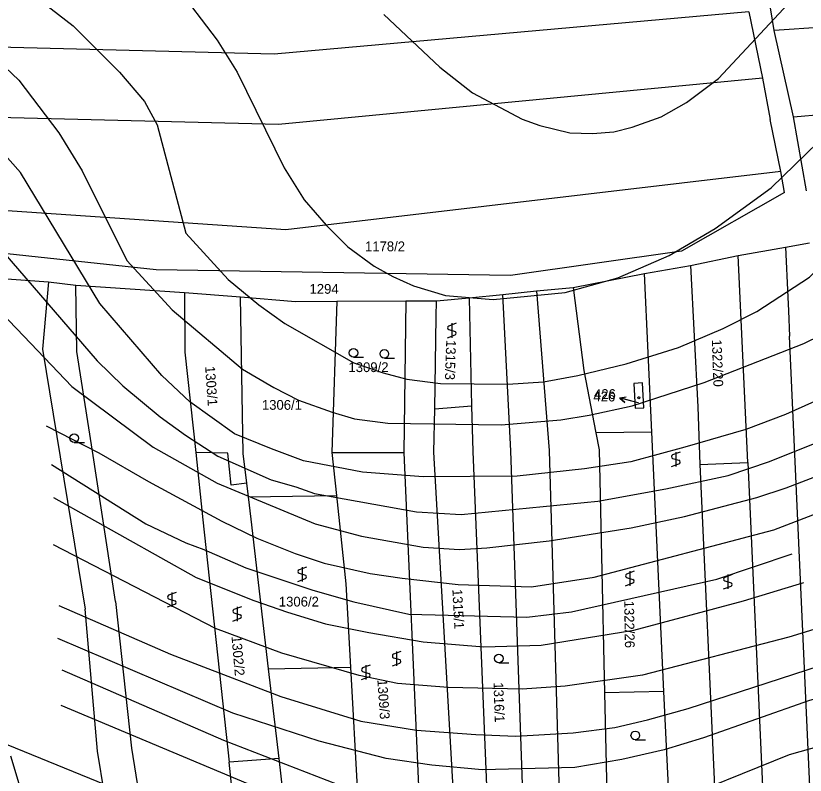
# Model space of a CAD drawing. Extents: x -555860 to -552701, y -1187050 to -1182291.
# Drawn here: x -554030 to -553892.9, y -1185037.6 to -1184905.7 of the extents above; entities that cross this region are included whole.
import ezdxf

# ---------------------------------------------------------------- set-up
doc = ezdxf.new("R2010")
doc.units = 0
for name, color, linetype in [('CYKLISTI_stav', 7, 'Continuous'), ('LEG_2b', 7, 'Continuous'), ('Level 16', 7, 'Continuous'), ('Level 25', 7, 'Continuous'), ('Level 40', 7, 'Continuous'), ('Level 41', 7, 'Continuous'), ('navrh_BV', 7, 'Continuous'), ('stav_BV', 7, 'Continuous')]:
    doc.layers.add(name, color=color, linetype=linetype)

msp = doc.modelspace()

# ---------------------------------------------------------------- linework, layer by layer
at = {"layer": 'CYKLISTI_stav'}
for p, q in [((-553921.18, -1184969.45), (-553922.68, -1184969.52)), ((-553922.68, -1184969.52), (-553922.47, -1184973.82)), ((-553920.98, -1184973.75), (-553921.18, -1184969.45)), ((-553922.47, -1184973.82), (-553920.98, -1184973.75))]:
    msp.add_line(p, q, dxfattribs=at)
at = {"layer": 'Level 16'}
for p, q in [((-553925.1, -1184972.09), (-553924.01, -1184971.85)), ((-553922.2, -1184972.84), (-553925.1, -1184972.09)), ((-553925.1, -1184972.09), (-553924.26, -1184972.82))]:
    msp.add_line(p, q, dxfattribs=at)
msp.add_lwpolyline([(-553921.89, -1184972.92), (-553922.2, -1184972.84)], dxfattribs=at)
at = {"layer": 'Level 25'}
for p, q in [((-553953.53, -1184959.09), (-553954.83, -1184959.56)), ((-553954.28, -1184959.09), (-553954.28, -1184961.59)), ((-553955.03, -1184961.59), (-553953.73, -1184961.1)), ((-553954.83, -1184960.17), (-553953.73, -1184960.5)), ((-553971.38, -1184964.95), (-553969.63, -1184964.95)), ((-553966.02, -1184965.15), (-553964.27, -1184965.15)), ((-554019.86, -1184979.8), (-554018.11, -1184979.8)), ((-553914.67, -1184981.47), (-553915.97, -1184981.95)), ((-553915.42, -1184981.47), (-553915.42, -1184983.97)), ((-553915.97, -1184982.55), (-553914.87, -1184982.88)), ((-553916.17, -1184983.97), (-553914.87, -1184983.48)), ((-553979.52, -1185001.42), (-553980.82, -1185001.9)), ((-553980.82, -1185002.5), (-553979.72, -1185002.83)), ((-553980.27, -1185001.42), (-553980.27, -1185003.92)), ((-553922.65, -1185002.16), (-553923.95, -1185002.64)), ((-553923.4, -1185002.16), (-553923.4, -1185004.66)), ((-553981.02, -1185003.92), (-553979.72, -1185003.43)), ((-553923.95, -1185003.24), (-553922.85, -1185003.57)), ((-553905.62, -1185002.73), (-553906.92, -1185003.21)), ((-553906.92, -1185003.81), (-553905.82, -1185004.14)), ((-553906.37, -1185002.73), (-553906.37, -1185005.23)), ((-553924.15, -1185004.66), (-553922.85, -1185004.17)), ((-553907.12, -1185005.23), (-553905.82, -1185004.74)), ((-554002.19, -1185005.85), (-554003.49, -1185006.32)), ((-554002.94, -1185005.85), (-554002.94, -1185008.35)), ((-554003.69, -1185008.35), (-554002.39, -1185007.86)), ((-554003.49, -1185006.93), (-554002.39, -1185007.26)), ((-553990.85, -1185008.31), (-553992.15, -1185008.78)), ((-553992.15, -1185009.39), (-553991.05, -1185009.72)), ((-553991.6, -1185008.31), (-553991.6, -1185010.81)), ((-553992.35, -1185010.81), (-553991.05, -1185010.32)), ((-553963.13, -1185016.09), (-553964.43, -1185016.56)), ((-553963.88, -1185016.09), (-553963.88, -1185018.59)), ((-553964.43, -1185017.17), (-553963.33, -1185017.5)), ((-553968.5, -1185018.47), (-553969.8, -1185018.95)), ((-553969.25, -1185018.47), (-553969.25, -1185020.97)), ((-553964.63, -1185018.59), (-553963.33, -1185018.1)), ((-553946.14, -1185018.04), (-553944.39, -1185018.04)), ((-553969.8, -1185019.55), (-553968.7, -1185019.88)), ((-553970, -1185020.97), (-553968.7, -1185020.48)), ((-553922.44, -1185031.4), (-553920.69, -1185031.4))]:
    msp.add_line(p, q, dxfattribs=at)
for centre, radius in [((-553971.38, -1184964.2), 0.75), ((-553966.02, -1184964.4), 0.75), ((-553921.84, -1184972.01), 0.175), ((-554019.86, -1184979.05), 0.75), ((-553946.14, -1185017.29), 0.75), ((-553922.44, -1185030.65), 0.75)]:
    msp.add_circle(centre, radius, dxfattribs=at)
for centre, start, end in [((-553954.7, -1184959.87), 113.579, 246.421), ((-553953.86, -1184960.8), 293.574, 66.426), ((-553915.84, -1184982.25), 113.579, 246.421), ((-553915, -1184983.18), 293.574, 66.426), ((-553980.69, -1185002.2), 113.579, 246.421), ((-553979.85, -1185003.13), 293.574, 66.426), ((-553923.82, -1185002.94), 113.579, 246.421), ((-553922.98, -1185003.87), 293.574, 66.426), ((-553906.79, -1185003.51), 113.579, 246.421), ((-553905.95, -1185004.44), 293.574, 66.426), ((-554003.36, -1185006.63), 113.579, 246.421), ((-554002.52, -1185007.56), 293.574, 66.426), ((-553992.02, -1185009.09), 113.579, 246.421), ((-553991.18, -1185010.02), 293.574, 66.426), ((-553964.3, -1185016.87), 113.579, 246.421), ((-553963.46, -1185017.8), 293.574, 66.426), ((-553969.67, -1185019.25), 113.579, 246.421), ((-553968.83, -1185020.18), 293.574, 66.426)]:
    msp.add_arc(centre, 0.329, start, end, dxfattribs=at)
at = {"layer": 'Level 40'}
for points in [[(-553846.88, -1184943.12), (-553856.95, -1184950.02), (-553865.7, -1184957.05), (-553875.27, -1184964.12), (-553882.93, -1184968.93), (-553896.35, -1184974.93), (-553903.23, -1184977.51), (-553913.82, -1184980.62), (-553923.19, -1184983.12), (-553931.29, -1184984.36), (-553942.94, -1184985.61), (-553959.3, -1184985.75), (-553969.84, -1184984.92), (-553980.08, -1184982.96), (-553985.64, -1184980.9), (-553992.02, -1184978.26), (-553999.79, -1184972.71), (-554004.64, -1184968.14), (-554015.45, -1184955.66), (-554029.18, -1184932.92), (-554034.17, -1184927.37)], [(-554023.46, -1184989.37), (-553998.68, -1185003.22), (-553988.69, -1185007.24), (-553982.85, -1185009.28), (-553976.25, -1185011.26), (-553968.73, -1185012.79), (-553959.26, -1185014.4), (-553948.76, -1185015.28), (-553938.78, -1185015), (-553922.69, -1185012.37), (-553903.68, -1185007.3), (-553893.18, -1185004.13)], [(-554022.18, -1185025.41), (-553989.8, -1185038.99), (-553977.32, -1185044.82), (-553969, -1185049.53), (-553958.76, -1185054.33), (-553952.37, -1185056.88), (-553948.86, -1185057.47), (-553939.61, -1185058.41), (-553931.9, -1185057.79), (-553926.02, -1185056.88), (-553916.59, -1185054.11), (-553894.27, -1185043.84), (-553880.54, -1185039.41), (-553873.48, -1185038.49), (-553866.4, -1185038.85), (-553841.44, -1185043.98), (-553838.37, -1185043.93), (-553834.92, -1185043.15), (-553828.96, -1185039.27), (-553800.95, -1185016.25)]]:
    msp.add_lwpolyline(points, dxfattribs=at)
at = {"layer": 'Level 41'}
for points in [[(-554029.46, -1184900.06), (-554020.03, -1184907.41), (-554011.99, -1184915.45), (-554007.69, -1184920.58), (-554005.47, -1184924.6), (-554000.48, -1184943.46), (-553993.13, -1184951.5), (-553987.84, -1184955.9), (-553983.29, -1184959.13), (-553971.34, -1184965.96), (-553966.23, -1184967.72), (-553962.1, -1184968.77), (-553956.25, -1184969.53), (-553944.6, -1184969.66), (-553938.37, -1184969.26), (-553932.4, -1184968.14), (-553924.02, -1184966.13), (-553914.93, -1184963.28), (-553907.19, -1184960.02), (-553901.34, -1184957.05), (-553892.19, -1184951.08), (-553878.57, -1184937.71)], [(-554002.28, -1184900.34), (-553995.07, -1184909.9), (-553991.6, -1184915.45), (-553983.42, -1184932.09), (-553979.96, -1184937.64), (-553976.12, -1184942.03), (-553972.33, -1184945.81), (-553967.76, -1184949.14), (-553964.57, -1184950.95), (-553960.96, -1184952.61), (-553955.42, -1184954.27), (-553947.1, -1184954.97), (-553934.62, -1184953.72), (-553925.47, -1184951.22), (-553916.59, -1184947.34), (-553908.55, -1184942.63), (-553898.84, -1184935.55), (-553890.69, -1184927.64)], [(-553966.09, -1184905.47), (-553956.39, -1184914.62), (-553950.7, -1184919.05), (-553942.1, -1184923.63), (-553939.03, -1184924.71), (-553933.79, -1184925.99), (-553929.9, -1184926.13), (-553926.16, -1184925.86), (-553922.97, -1184925.02), (-553917.98, -1184923.21), (-553913.54, -1184920.72), (-553907.99, -1184916.56), (-553893.49, -1184900.97)], [(-554037.78, -1184909.07), (-554029.46, -1184916.84), (-554022.53, -1184925.99), (-554018.51, -1184932.64), (-554010.74, -1184948.17), (-554002.84, -1184956.77), (-553990.64, -1184967.03), (-553985.2, -1184970.25), (-553980.93, -1184972.44), (-553975.1, -1184974.52), (-553971.18, -1184975.7), (-553965.4, -1184976.46), (-553945.71, -1184976.74), (-553935.4, -1184975.86), (-553930.46, -1184975.07), (-553922.97, -1184973.41), (-553910.49, -1184969.39), (-553893.16, -1184962.59), (-553884.42, -1184958.29)], [(-554037.08, -1184941.1), (-554015.89, -1184965.63), (-554011.43, -1184969.94), (-554004.92, -1184975.35), (-554000.55, -1184978.5), (-553994.93, -1184982.14), (-553985.7, -1184986.26), (-553981.37, -1184987.5), (-553978.16, -1184988.66), (-553960.41, -1184991.85), (-553952.66, -1184992.29), (-553928.93, -1184989.98), (-553917.15, -1184987.83), (-553906.32, -1184985.52), (-553899.12, -1184983.11), (-553887.72, -1184978.5), (-553878.05, -1184974.24), (-553865.11, -1184966.46), (-553856.83, -1184961.07), (-553838.49, -1184947.41)], [(-554044.57, -1184944.71), (-554028.63, -1184961.34), (-554020.31, -1184970.08), (-554006.16, -1184980.62), (-553995.07, -1184986.86), (-553978.02, -1184993.93), (-553969.98, -1184996.08), (-553959.3, -1184997.95), (-553952.98, -1184998.39), (-553948.21, -1184998.09), (-553937.39, -1184996.84), (-553923.15, -1184994.6), (-553913.91, -1184992.62), (-553901.34, -1184989.35), (-553896.26, -1184987.67), (-553887.33, -1184984.22), (-553866.81, -1184975.63), (-553856.83, -1184970.64), (-553837.97, -1184957.88), (-553831.32, -1184953.92), (-553823, -1184949.56), (-553815.94, -1184946.67)], [(-554024.76, -1184976.88), (-554015.59, -1184981.59), (-554006.98, -1184986.59), (-553994.24, -1184993.44), (-553988.14, -1184996.43), (-553981.53, -1184999.05), (-553976.49, -1185000.72), (-553968.5, -1185002.52), (-553962.9, -1185003.36), (-553953.2, -1185004.47), (-553940.44, -1185004.88), (-553929.59, -1185003.18), (-553898.4, -1184994.93), (-553882.89, -1184988.99), (-553868.24, -1184982.79), (-553853.23, -1184977.02), (-553838.11, -1184966.48), (-553825.08, -1184958.99), (-553814.82, -1184954.57), (-553806.5, -1184951.22), (-553801.95, -1184950.12)], [(-553748.88, -1184982.14), (-553757.97, -1184976.46), (-553763.99, -1184974.21), (-553770.17, -1184972.57), (-553776.86, -1184972.07), (-553781.82, -1184971.88), (-553788.58, -1184972.73), (-553795.13, -1184973.96), (-553805.11, -1184977.43), (-553816.2, -1184982.7), (-553837.56, -1184994.07), (-553851.15, -1184999.89), (-553895.79, -1185013.62), (-553921.17, -1185020.17), (-553934.62, -1185022.08), (-553942.1, -1185022.63), (-553954.96, -1185022.32), (-553963.73, -1185021.66), (-553970.39, -1185020.27), (-553983.84, -1185016.38), (-553995.35, -1185012.09), (-554023.46, -1184997.58)], [(-554022.56, -1185008.07), (-554003.15, -1185016.54), (-553983.98, -1185023.88), (-553970.11, -1185028.18), (-553960.41, -1185029.74), (-553950.15, -1185030.53), (-553943.21, -1185030.81), (-553933.22, -1185030.24), (-553926.02, -1185029.29), (-553920.35, -1185027.93), (-553913.26, -1185025.96), (-553885.81, -1185017.08), (-553874.16, -1185014.03), (-553856.69, -1185011.12), (-553846.99, -1185008.63), (-553830.35, -1185001.83), (-553804.28, -1184987.55), (-553789.86, -1184981.86)], [(-554023.83, -1184983.59), (-554007.41, -1184993.93), (-554000.51, -1184997.24), (-553997.37, -1184998.39), (-553990.08, -1185001.55), (-553978.43, -1185005.44), (-553971.3, -1185007.47), (-553961.79, -1185009.6), (-553941.27, -1185010.15), (-553933.51, -1185009.18), (-553908.27, -1185003.5), (-553895.23, -1184999.15)], [(-553798.18, -1184992.68), (-553811.77, -1184999.06), (-553835.89, -1185013.9), (-553841.72, -1185016.53), (-553845.8, -1185018.03), (-553859.19, -1185019.72), (-553872.78, -1185020.14), (-553878.6, -1185020.97), (-553892.19, -1185024.57), (-553910.61, -1185031.06), (-553917.42, -1185033.17), (-553924.8, -1185034.86), (-553932.95, -1185036.22), (-553949.04, -1185036.64), (-553957.77, -1185035.85), (-553965.68, -1185034.69), (-553977.32, -1185031.64), (-553992.3, -1185026.79), (-554022.74, -1185013.85)], [(-554022, -1185019.26), (-553993.96, -1185031.5), (-553963.46, -1185043.29), (-553953.47, -1185046.48), (-553949.35, -1185047.23), (-553941.27, -1185047.45), (-553932.56, -1185046.57), (-553926.02, -1185045.09), (-553917.7, -1185042.87), (-553895.65, -1185034), (-553884.98, -1185030.95), (-553873.33, -1185029.01), (-553868.86, -1185028.92), (-553863.9, -1185029.29), (-553857.8, -1185030.12), (-553849.48, -1185030.95), (-553844.21, -1185030.67), (-553838.39, -1185029.43), (-553832.6, -1185027.27), (-553828.27, -1185024.99), (-553810.66, -1185009.88), (-553801.37, -1185003.36)], [(-554002.98, -1185043.93), (-554038.61, -1185029.43)]]:
    msp.add_lwpolyline(points, dxfattribs=at)
at = {"layer": 'navrh_BV'}
for p, q in [((-553898.35, -1184908.26), (-553900.51, -1184894.48)), ((-553902.74, -1184905), (-553985.15, -1184912.34)), ((-553902.74, -1184905), (-553900.36, -1184916.5)), ((-553841.58, -1184904.41), (-553898.35, -1184908.26)), ((-553894.95, -1184923.21), (-553898.35, -1184908.26)), ((-553985.15, -1184912.34), (-554037.67, -1184911.01)), ((-553900.36, -1184916.5), (-553984.42, -1184924.58)), ((-553900.36, -1184916.5), (-553899.04, -1184923.67)), ((-553894.95, -1184923.21), (-553841.03, -1184918.7)), ((-553984.42, -1184924.58), (-554037.31, -1184923.26)), ((-553897.19, -1184932.74), (-553899.04, -1184923.67)), ((-553892.7, -1184936.1), (-553894.95, -1184923.21)), ((-553897.19, -1184932.74), (-553983.1, -1184942.85)), ((-553896.54, -1184936.39), (-553897.19, -1184932.74)), ((-553896.54, -1184936.39), (-553914.4, -1184946.57)), ((-553983.1, -1184942.85), (-554037.78, -1184939.14)), ((-554005.64, -1184949.81), (-554060.2, -1184943.98)), ((-553904.57, -1184947.31), (-553896.35, -1184945.85)), ((-553896.35, -1184945.85), (-553892.21, -1184945.11)), ((-553896.35, -1184945.85), (-553895.96, -1184954.54)), ((-553914.4, -1184946.57), (-553944.13, -1184950.79)), ((-553912.83, -1184949.06), (-553904.57, -1184947.31)), ((-553902.92, -1184983.27), (-553904.57, -1184947.31)), ((-553920.87, -1184950.42), (-553912.83, -1184949.06)), ((-553912.83, -1184949.06), (-553911.57, -1184973.61)), ((-553944.13, -1184950.79), (-554005.64, -1184949.81)), ((-553933.25, -1184952.85), (-553920.87, -1184950.42)), ((-553919.58, -1184977.99), (-553920.87, -1184950.42)), ((-554034.8, -1184951.16), (-554024.31, -1184951.89)), ((-554024.31, -1184951.89), (-554025.35, -1184963.6)), ((-554024.31, -1184951.89), (-554019.59, -1184952.44)), ((-554019.4, -1184963.98), (-554019.59, -1184952.44)), ((-554019.59, -1184952.44), (-554000.7, -1184953.73)), ((-553939.61, -1184953.44), (-553933.25, -1184952.85)), ((-553933.25, -1184952.85), (-553931.4, -1184967.26)), ((-554000.7, -1184953.73), (-553990.98, -1184954.51)), ((-554000.7, -1184953.73), (-554000.67, -1184964.1)), ((-553990.51, -1184981.71), (-553990.98, -1184954.51)), ((-553990.98, -1184954.51), (-553981.44, -1184955.31)), ((-553951.28, -1184954.65), (-553945.43, -1184954.06)), ((-553945.43, -1184954.06), (-553939.61, -1184953.44)), ((-553944.07, -1184981.21), (-553945.43, -1184954.06)), ((-553939.61, -1184953.44), (-553937.42, -1184981.19)), ((-553895.96, -1184954.54), (-553895.85, -1184956.94)), ((-553981.44, -1184955.31), (-553974.28, -1184955.24)), ((-553974.28, -1184955.24), (-553975.11, -1184981.53)), ((-553974.28, -1184955.24), (-553962.26, -1184955.2)), ((-553962.26, -1184955.2), (-553962.63, -1184981.53)), ((-553962.26, -1184955.2), (-553956.95, -1184955.17)), ((-553957, -1184957.97), (-553956.95, -1184955.17)), ((-553956.95, -1184955.17), (-553951.28, -1184954.65)), ((-553951.28, -1184954.65), (-553951.22, -1184957.45)), ((-553895.85, -1184956.94), (-553895.66, -1184961.33)), ((-553957.27, -1184973.96), (-553957, -1184957.97)), ((-553951.22, -1184957.45), (-553950.86, -1184973.45)), ((-553886.1, -1185174.65), (-553895.66, -1184961.33)), ((-554025.35, -1184963.6), (-554017.99, -1185008.76)), ((-554016.71, -1184981.32), (-554019.4, -1184963.98)), ((-554000.67, -1184964.1), (-553998.78, -1184981.55)), ((-553931.4, -1184967.26), (-553929.29, -1184978.13)), ((-553957.27, -1184973.96), (-553950.86, -1184973.45)), ((-553950.86, -1184973.45), (-553950.68, -1184981.36)), ((-553911.57, -1184973.61), (-553911.25, -1184983.62)), ((-553957.4, -1184981.46), (-553957.27, -1184973.96)), ((-553919.58, -1184977.99), (-553929.29, -1184978.13)), ((-553929.29, -1184978.13), (-553928.72, -1184981.05)), ((-553917.47, -1185023.04), (-553919.58, -1184977.99)), ((-554012.68, -1185007.4), (-554016.71, -1184981.32)), ((-553993.21, -1184981.66), (-553998.78, -1184981.55)), ((-553998.78, -1184981.55), (-553997.52, -1184993.23)), ((-553992.59, -1184987.19), (-553993.21, -1184981.66)), ((-553989.9, -1184986.87), (-553990.51, -1184981.71)), ((-553975.11, -1184981.53), (-553968.87, -1184981.53)), ((-553975.11, -1184981.53), (-553974.33, -1184988.99)), ((-553968.87, -1184981.53), (-553962.63, -1184981.53)), ((-553962.63, -1184981.53), (-553959.52, -1185052.86)), ((-553953.9, -1185042.96), (-553957.4, -1184981.46)), ((-553950.68, -1184981.36), (-553948.18, -1185042.53)), ((-553941.56, -1185051.56), (-553944.07, -1184981.21)), ((-553937.42, -1184981.19), (-553935.35, -1185051.09)), ((-553928.72, -1184981.05), (-553928.31, -1184999.51)), ((-553911.25, -1184983.62), (-553902.92, -1184983.27)), ((-553902.92, -1184983.27), (-553900.22, -1185042.37)), ((-553911.25, -1184983.62), (-553908.55, -1185042.75)), ((-553989.9, -1184986.87), (-553992.59, -1184987.19)), ((-553989.62, -1184989.25), (-553989.9, -1184986.87)), ((-553989.62, -1184989.25), (-553974.33, -1184988.99)), ((-553989.17, -1184993.13), (-553989.62, -1184989.25)), ((-553974.33, -1184988.99), (-553972.73, -1185004.33)), ((-553997.52, -1184993.23), (-553992.97, -1185035.28)), ((-553986.12, -1185019.11), (-553989.17, -1184993.13)), ((-553928.31, -1184999.51), (-553927.77, -1185023.24)), ((-553972.73, -1185004.33), (-553971.92, -1185018.81)), ((-554012.68, -1185007.4), (-554009.94, -1185032.87)), ((-554015.81, -1185033.41), (-554017.99, -1185008.76)), ((-553986.12, -1185019.11), (-553971.92, -1185018.81)), ((-553971.92, -1185018.81), (-553969.95, -1185053.65)), ((-553984.29, -1185034.66), (-553986.12, -1185019.11)), ((-553917.47, -1185023.04), (-553927.77, -1185023.24)), ((-553916.25, -1185048.91), (-553917.47, -1185023.04)), ((-553927.77, -1185023.24), (-553927.18, -1185049.56)), ((-554010.76, -1185064.19), (-554015.81, -1185033.41)), ((-554009.94, -1185032.87), (-554002.29, -1185078.89)), ((-554016.37, -1185082.26), (-554030.87, -1185034.29)), ((-553984.29, -1185034.66), (-553992.97, -1185035.28)), ((-553990.82, -1185055.17), (-553992.97, -1185035.28)), ((-553981.96, -1185054.52), (-553984.29, -1185034.66))]:
    msp.add_line(p, q, dxfattribs=at)
at = {"layer": 'stav_BV'}
for p, q in [((-553925.1, -1184972.06), (-553924, -1184971.84)), ((-553922.2, -1184972.84), (-553925.1, -1184972.06)), ((-553925.1, -1184972.06), (-553924.26, -1184972.81)), ((-553921.89, -1184972.92), (-553922.2, -1184972.84))]:
    msp.add_line(p, q, dxfattribs=at)

# ---------------------------------------------------------------- texts
at = {"layer": 'LEG_2b'}
for s, p in [('1178/2', (-553969.38, -1184946.58)), ('1294', (-553979.01, -1184953.96)), ('1309/2', (-553972.25, -1184967.56)), ('426', (-553929.72, -1184972.66)), ('1306/1', (-553987.28, -1184974.11)), ('1306/2', (-553984.34, -1185008.28))]:
    msp.add_text(s, height=1.7, dxfattribs=at).set_placement(p)
for s, rotation, p in [('1315/3', 268, (-553955.26, -1184961.96)), ('1322/20', 272, (-553909.15, -1184961.93)), ('1303/1', 274, (-553997.14, -1184966.57)), ('1315/1', 273, (-553954.21, -1185005.3)), ('1322/26', 271, (-553924.38, -1185007.28)), ('1302/2', 275, (-553992.56, -1185013.47)), ('1309/3', 274, (-553967.24, -1185020.98)), ('1316/1', 272, (-553947.07, -1185021.47))]:
    msp.add_text(s, height=1.7, rotation=rotation, dxfattribs=at).set_placement(p)
at = {"layer": 'Level 16'}
msp.add_text('426', height=1.7, dxfattribs=at).set_placement((-553929.62, -1184972.23))

doc.saveas('drawing.dxf')
